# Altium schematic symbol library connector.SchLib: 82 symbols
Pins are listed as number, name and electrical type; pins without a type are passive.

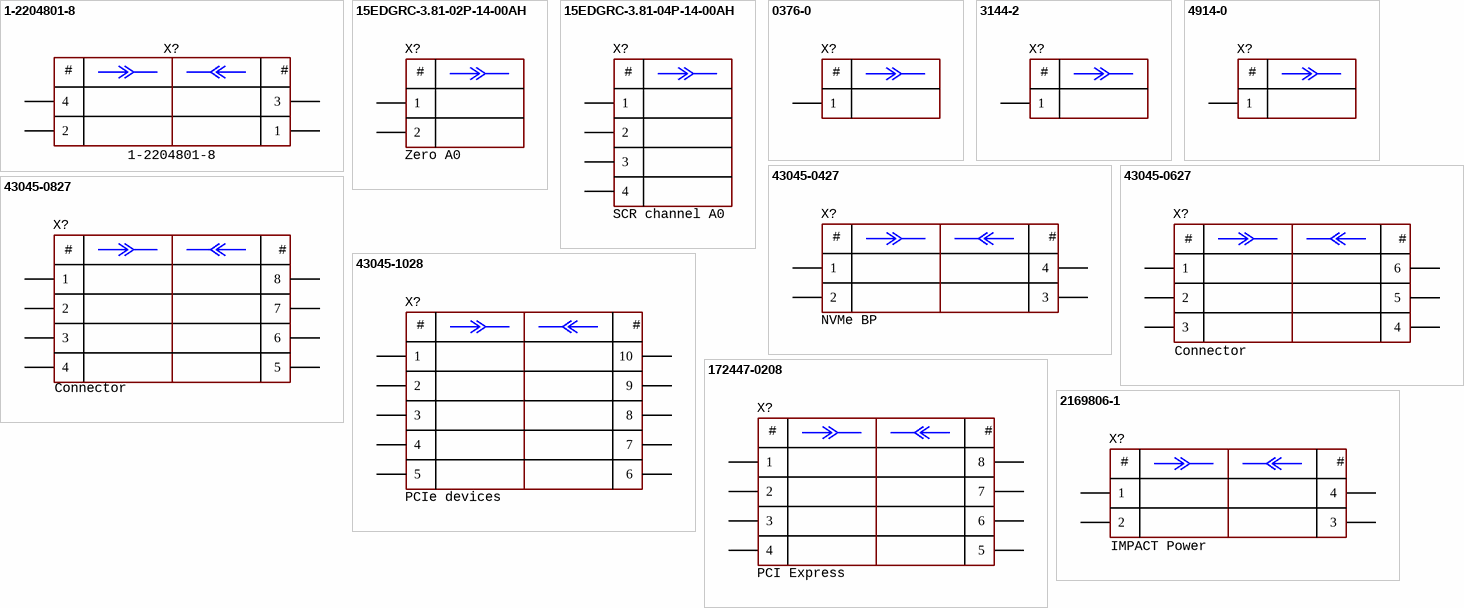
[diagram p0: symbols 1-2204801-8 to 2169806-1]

## 1-2204801-8
designator X?
MicroFit, 4 pins, pitch 3.0 mm, 600V, 12.5A/pin, -40...+105°C; Manufacturer: TE Connectivity
footprint CON: 1-2204801-8 (MicroFit)
pins: 1, 2, 3, 4

## 15EDGRC-3.81-02P-14-00AH
designator X?, comment Zero A0
Terminal, 2 pins, pitch 3.81 mm, 8A/pin, 500VAC; PartNumber: 15EDGRC-3.81-02P-14-00AH; Manufacturer: Degson; Pitch: 3.81 mm
footprint CON: 15EDGRC-3.81-02P-14-00AH (Degson) (PLS-4 pin header)
pins: 1, 2

## 15EDGRC-3.81-04P-14-00AH
designator X?, comment SCR channel A0
Terminal, 4 pins, pitch 3.81 mm, 8A/pin, 500VAC; Manufacturer: Degson; PartNumber: 15EDGRC-3.81-04P-14-00AH; Pitch: 3.81 mm
footprint CON: 15EDGRC-3.81-04P-14-00AH (Degson) (PLS-4 pin header)
pins: 1, 2, 3 (power), 4 (power)

## 0376-0
designator X?
Power Pin, SMT, -55...+150°C; PartNumber: 0376-0-43-80-07-27-10-0; Manufacturer: Mill-Max
footprint CON: 0376-0 (Mill-Max)
pins: 1

## 3144-2
designator X?
Power Pin, SMT, -55...+150°C; PartNumber: 3144-2-00-15-00-00-08-0; Manufacturer: Mill-Max
footprint CON: 3144-2 (Mill-Max)
pins: 1

## 4914-0
designator X?
Power Pin, SMT, -55...+150°C; PartNumber: 4914-0-00-15-00-00-03-0; Manufacturer: Mill-Max
footprint CON: 4914-0 (Mill-Max)
pins: 1

## 43045-0427
designator X?, comment NVMe BP
MicroFit, 4 pins, pitch 3.0 mm, 600V, 8.5A/pin, -40...+105°C; PartNumber: 43045-0427; Manufacturer: Molex
footprint CON: 43045-0427 (MicroFit)
pins: 1, 2, 3, 4

## 43045-0627
designator X?, comment Connector
MicroFit, 6 pins, pitch 3.0 mm, 600V, 8.5A/pin, -40...+105°C; PartNumber: 43045-0627; Manufacturer: Molex
footprint CON: 43045-0628 (MicroFit)
pins: 1, 2, 3, 4, 5, 6

## 43045-0827
designator X?, comment Connector
MicroFit, 8 pins, pitch 3.0 mm, 600V, 8.5A/pin, -40...+105°C; PartNumber: 43045-0827; Manufacturer: Molex
footprint CON: 43045-0828 (MicroFit)
pins: 1, 2, 3, 4, 5, 6, 7, 8

## 43045-1028
designator X?, comment PCIe devices
MicroFit, 10 pins, pitch 3.0 mm, 600V, 8.5A/pin, -40...+105°C; PartNumber: 43045-1028; Manufacturer: Molex
footprint CON: 43045-1028 (MicroFit)
pins: 1, 2, 3, 4, 5, 6, 7, 8, 9, 10

## 172447-0208
designator X?, comment PCI Express
MiniFit, 8 pins, pitch 4.2 mm, 600V, 9A/pin, -40...+105°C; Manufacturer: Molex; PartNumber: 172447-0208; Manufacturer: Molex Waldom
footprint CON: 172447-0208
pins: 1, 2, 3, 4, 5, 6, 7, 8

## 2169806-1
designator X?  Package: IMPACT Power  (hidden comment: 2169806-1)
IMPACT, 4 pins, pitch 5.2 mm, 48V, 15A/pin, -55...+85°C; Manufacturer: TE Connectivity
footprint CON: 2169806-1
pins: 1, 2, 3, 4

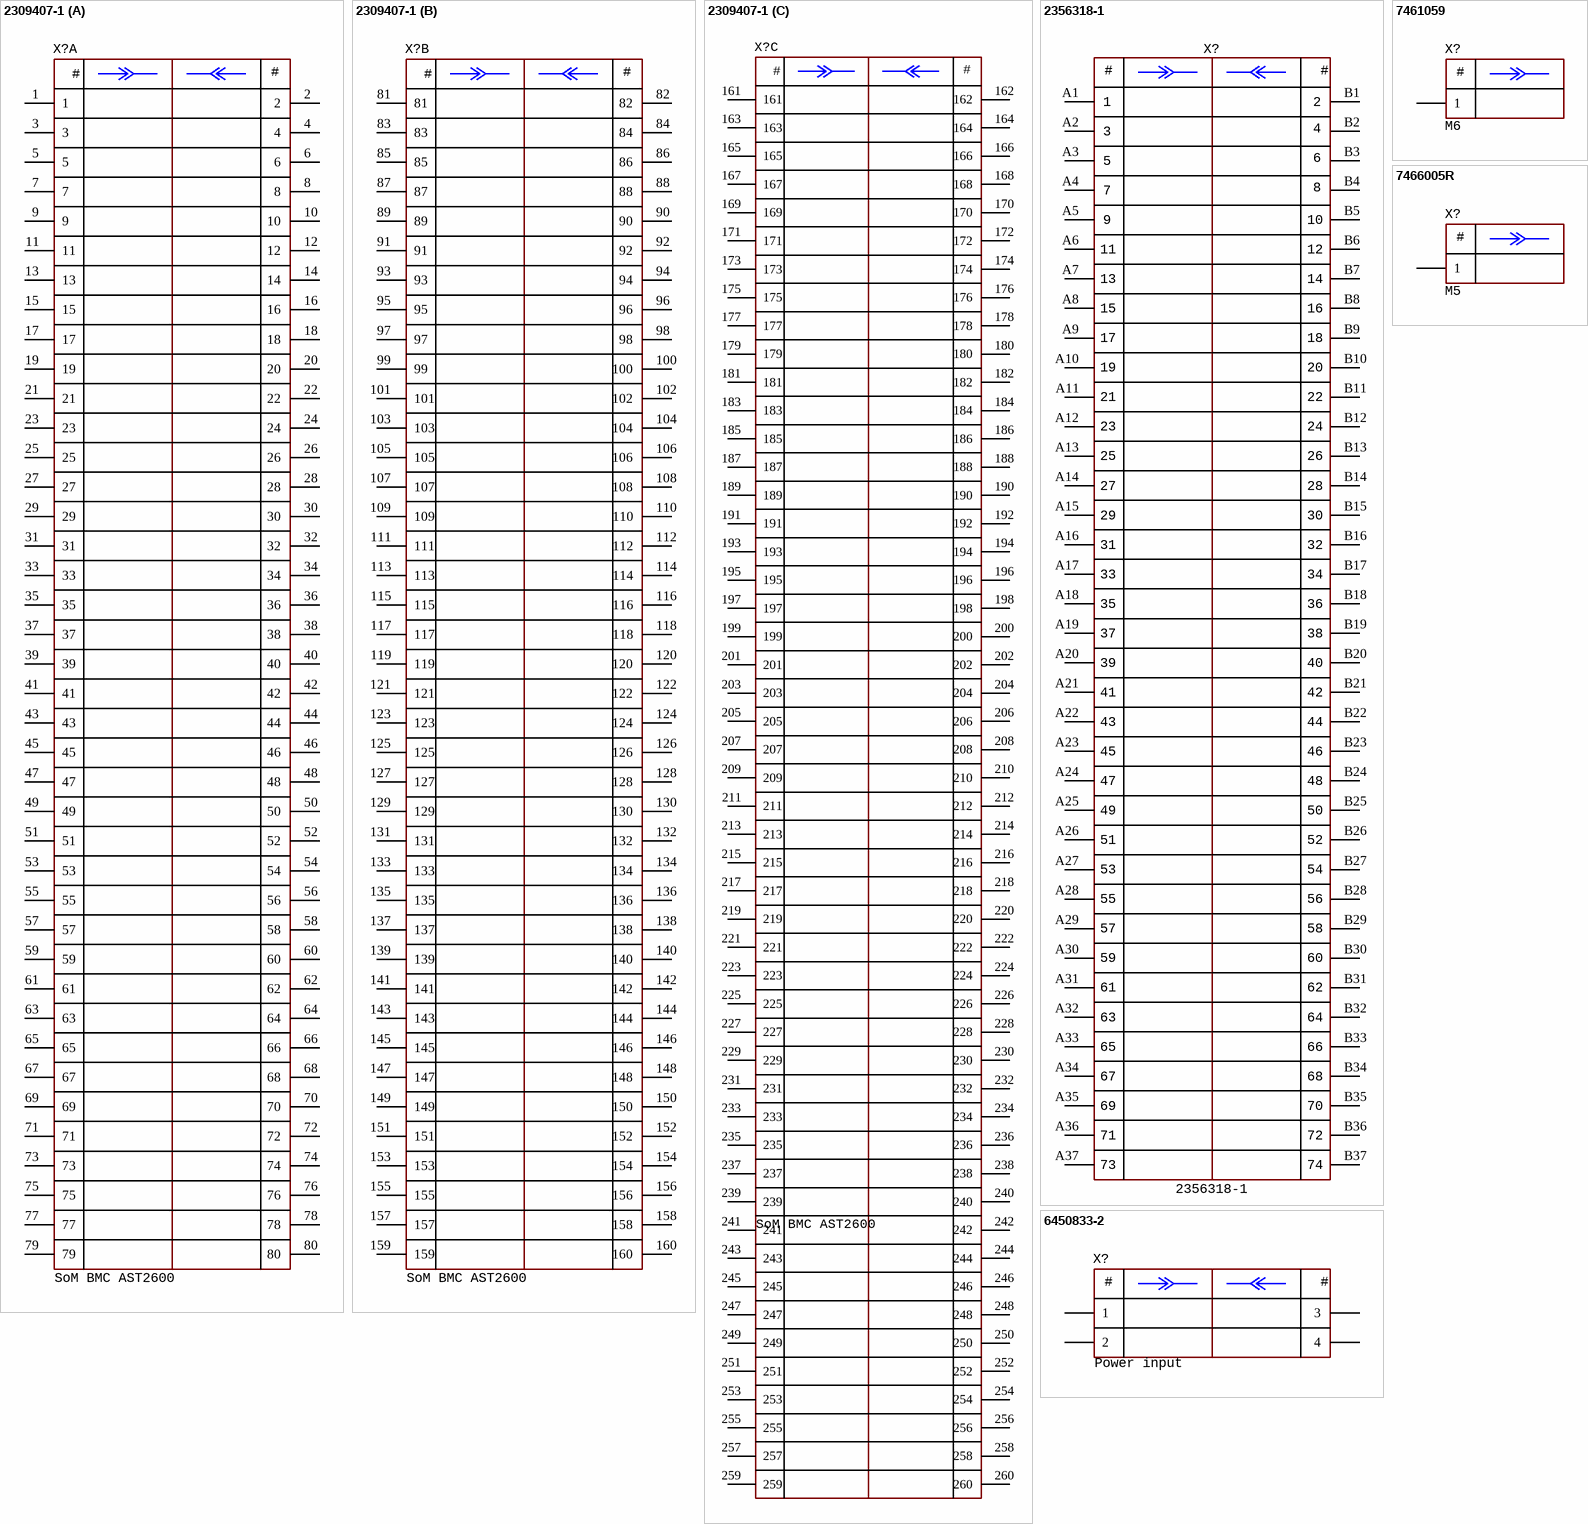
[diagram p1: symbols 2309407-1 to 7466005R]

## 2309407-1
designator X?, comment SoM BMC AST2600
SODIMM DDR4, 260 pins, pitch 0.5 mm, 0.5A/pin, Right Angle, -55...+85C; Manufacturer: TE connectivity; PartNumber: 2309407-1; Pitch: 0.5mm
footprint CON: 2309407-1 (TE, SODIMM DDR4)
part A pins: 1, 2, 3, 4, 5, 6, 7, 8, 9, 10, 11, 12, 13, 14, 15, 16, 17, 18, 19, 20, 21, 22, 23, 24, 25, 26, 27, 28, 29, 30, 31, 32, 33, 34, 35, 36, 37, 38, 39, 40, 41, 42, 43, 44, 45, 46, 47, 48, 49, 50, 51, 52, 53, 54, 55, 56, 57, 58, 59, 60, 61, 62, 63, 64, 65, 66, 67, 68, 69, 70, 71, 72, 73, 74, 75, 76, 77, 78, 79, 80
part B pins: 81, 82, 83, 84, 85, 86, 87, 88, 89, 90, 91, 92, 93, 94, 95, 96, 97, 98, 99, 100, 101, 102, 103, 104, 105, 106, 107, 108, 109, 110, 111, 112, 113, 114, 115, 116, 117, 118, 119, 120, 121, 122, 123, 124, 125, 126, 127, 128, 129, 130, 131, 132, 133, 134, 135, 136, 137, 138, 139, 140, 141, 142, 143, 144, 145, 146, 147, 148, 149, 150, 151, 152, 153, 154, 155, 156, 157, 158, 159, 160
part C pins: 161, 162, 163, 164, 165, 166, 167, 168, 169, 170, 171, 172, 173, 174, 175, 176, 177, 178, 179, 180, 181, 182, 183, 184, 185, 186, 187, 188, 189, 190, 191, 192, 193, 194, 195, 196, 197, 198, 199, 200, 201, 202, 203, 204, 205, 206, 207, 208, 209, 210, 211, 212, 213, 214, 215, 216, 217, 218, 219, 220, 221, 222, 223, 224, 225, 226, 227, 228, 229, 230, 231, 232, 233, 234, 235, 236, 237, 238, 239, 240, 241, 242, 243, 244, 245, 246, 247, 248, 249, 250, 251, 252, 253, 254, 255, 256, 257, 258, 259, 260

## 2356318-1
designator X?
SlimSAS, x8 line, 74 pins, 0.5A/pin, SFF-8654, vertical, -55...+85°C; Manufacturer: TE connectivity; Manufacturer: TE Connectivity AMP; Multichannel: 74pin
footprint CON: 2356318-1 (SlimSAS)
pins: A1, A2, A3, A4, A5, A6, A7, A8, A9, A10, A11, A12, A13, A14, A15, A16, A17, A18, A19, A20, A21, A22, A23, A24, A25, A26, A27, A28, A29, A30, A31, A32, A33, A34, A35, A36, A37, B1, B2, B3, B4, B5, B6, B7, B8, B9, B10, B11, B12, B13, B14, B15, B16, B17, B18, B19, B20, B21, B22, B23, B24, B25, B26, B27, B28, B29, B30, B31, B32, B33, B34, B35, B36, B37

## 6450833-2
designator X?, comment Power input
Power, 4 pins, pitch 6.35 mm, 200V, 50A/pin, -40...+125°C; PartNumber: 6450833-2; Manufacturer: TE connectivity
footprint CON: 6450833-2
pins: 1, 2, 3, 4

## 7461059
designator X?, comment M6
Power, 240A, screw M6, SMT, -55...+150°C; Manufacturer: Wurth; PartNumber: 7461059; Manufacturer: Wurth Electronics; Manufacturer Part Number: 746105-9
footprint CON: 7461059 (Wurth, connector)
pins: 1

## 7466005R
designator X?, comment M5
Power, 70A, screw M5, SMT, -55...+150°C; PartNumber: 7466005R; Manufacturer: Wurth; Manufacturer: Wurth Electronics
footprint CON: 7466005R (Wurth, connector)
pins: 1

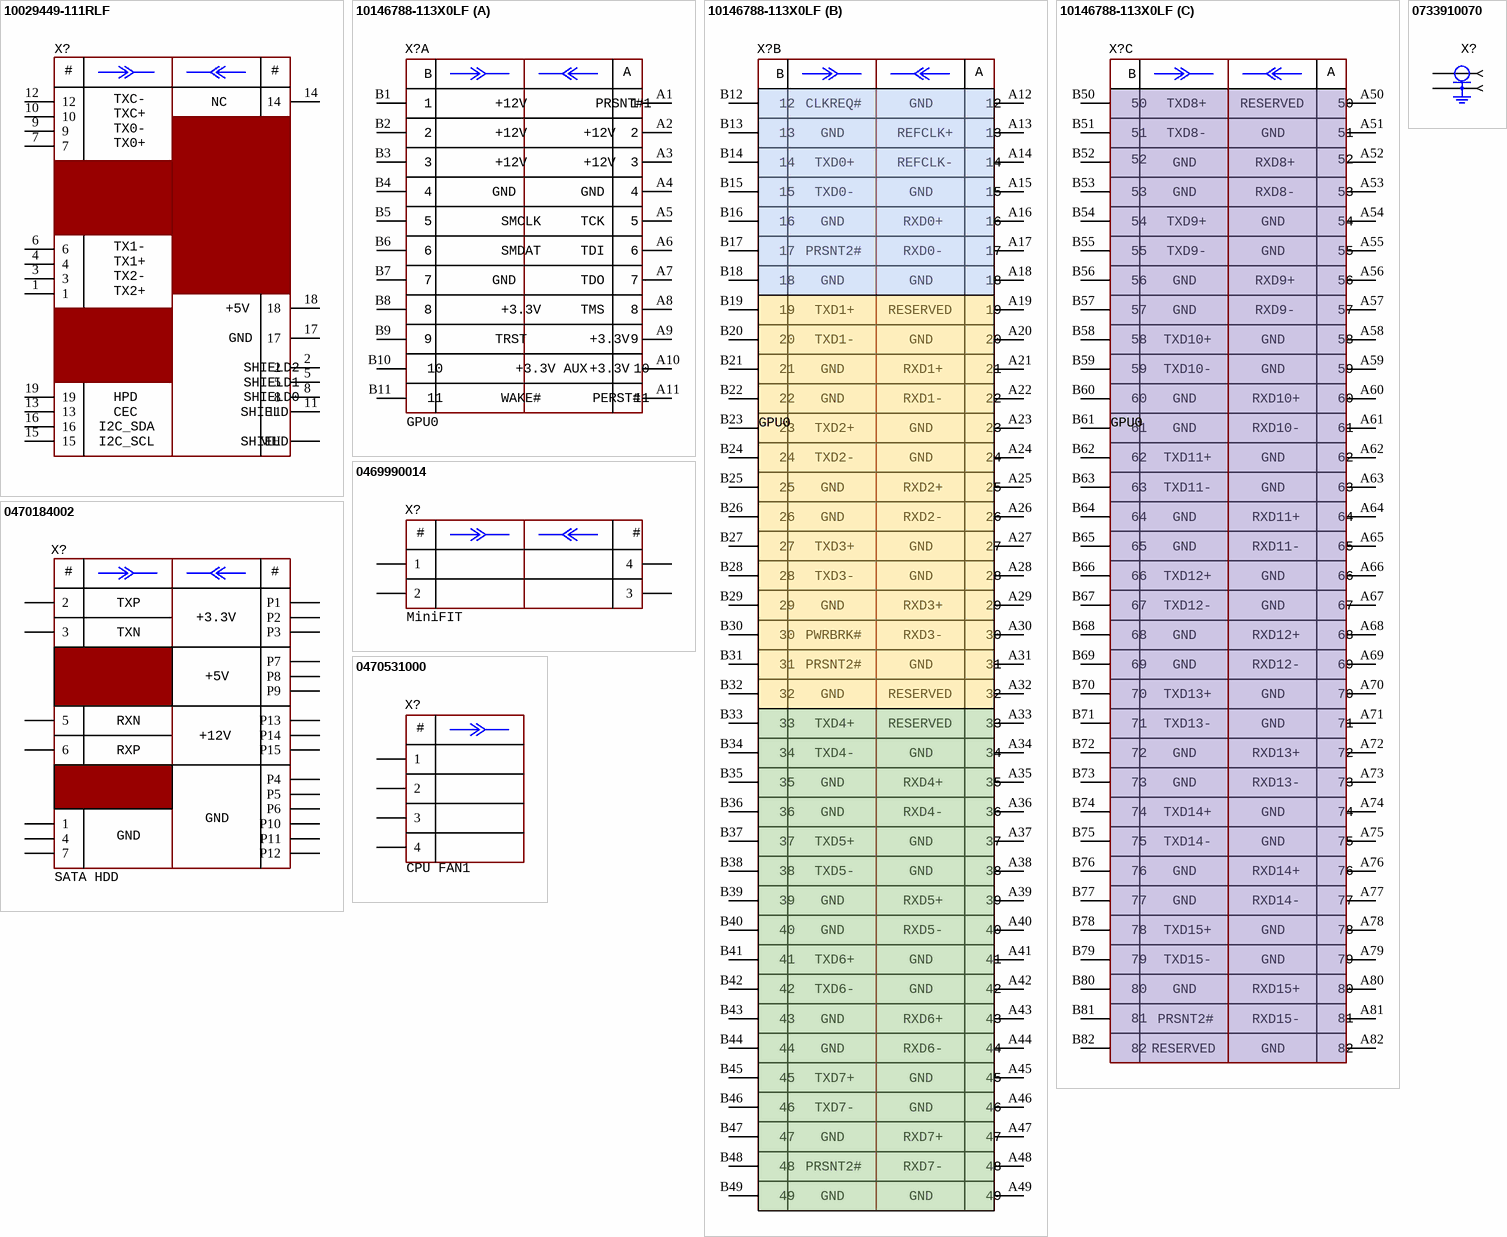
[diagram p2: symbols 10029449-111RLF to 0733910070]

## 10029449-111RLF
designator X?  (value not drawn)
HDMI 1.4, 0.5A/pin, 19 pins, -20...+85°C
footprint CON: HDMI_10029449-111RLF (HDMI 1.4, Amphenol)
pins: 1, 2, 3, 4, 5, 6, 7, 8, 9, 10, 11, 12, 13, 14, 15, 16, 17, 18, 19, MH (power)

## 10146788-113X0LF
designator X?, comment GPU0
PCI Express, Gen 4.0, x16 lines, 16 GT/s, 164 pins, pitch 1.0 mm, -40...+85°C; Manufacturer: Amphenol; PartNumber: 10146788-113X0LF
footprint CON: 10146788-113X0LF (PCIe gen 4, Amphenol)
part A pins: A1, A2, A3, A4, A5, A6, A7, A8, A9, A10, A11, B1, B2, B3, B4, B5, B6, B7, B8, B9, B10, B11
part B pins: A12, A13, A14, A15, A16, A17, A18, A19, A20, A21, A22, A23, A24, A25, A26, A27, A28, A29, A30, A31, A32, A33, A34, A35, A36, A37, A38, A39, A40, A41, A42, A43, A44, A45, A46, A47, A48, A49, B12, B13, B14, B15, B16, B17, B18, B19, B20, B21, B22, B23, B24, B25, B26, B27, B28, B29, B30, B31, B32, B33, B34, B35, B36, B37, B38, B39, B40, B41, B42, B43, B44, B45, B46, B47, B48, B49
part C pins: A50, A51, A52, A53, A54, A55, A56, A57, A58, A59, A60, A61, A62, A63, A64, A65, A66, A67, A68, A69, A70, A71, A72, A73, A74, A75, A76, A77, A78, A79, A80, A81, A82, B50, B51, B52, B53, B54, B55, B56, B57, B58, B59, B60, B61, B62, B63, B64, B65, B66, B67, B68, B69, B70, B71, B72, B73, B74, B75, B76, B77, B78, B79, B80, B81, B82

## 0469990014
designator X?, comment MiniFIT
MiniFit, 4 pins, pitch 4.2 mm, 600V, 20A/pin, -40...+105°C; PartNumber: 0469990014; Manufacturer: Molex; Manufacturer Part Number: 172447-0206
footprint CON: 0469990014 (MiniFitm 4 pins, 90)
pins: 1, 2, 3, 4

## 0470184002
designator X?, comment SATA HDD
SATA HDD, 7+15 pins, 24 GT/s, Right angle, -55...+85°C; Manufacturer: Molex; PartNumber: 0470184002; Multichannel: 74pin
footprint CON: 0470184002 (Molex, SATA HDD)
pins: 1, 2, 3, 4, 5, 6, 7, P1, P2, P3, P4, P5, P6, P7, P8, P9, P10, P11, P12, P13, P14, P15

## 0470531000
designator X?, comment CPU FAN1
Fan, 4 pins, pitch 2.54 mm, 3A/pins, 600V, -40...+125°C; PartNumber: 0470531000; Manufacturer: Molex; Pitch: 2.54mm
footprint CON: 0470531000 (Molex, CPU fan)
pins: 1, 2, 3, 4 (power)

## 0733910070
designator X?, comment SMA  (value not drawn)
SMA, RF type, 50 Ohms, 18GHz, -40...+125°C; PartNumber: 0733910070; Manufacturer: Molex
footprint CON: SMA
pins: 1, 2

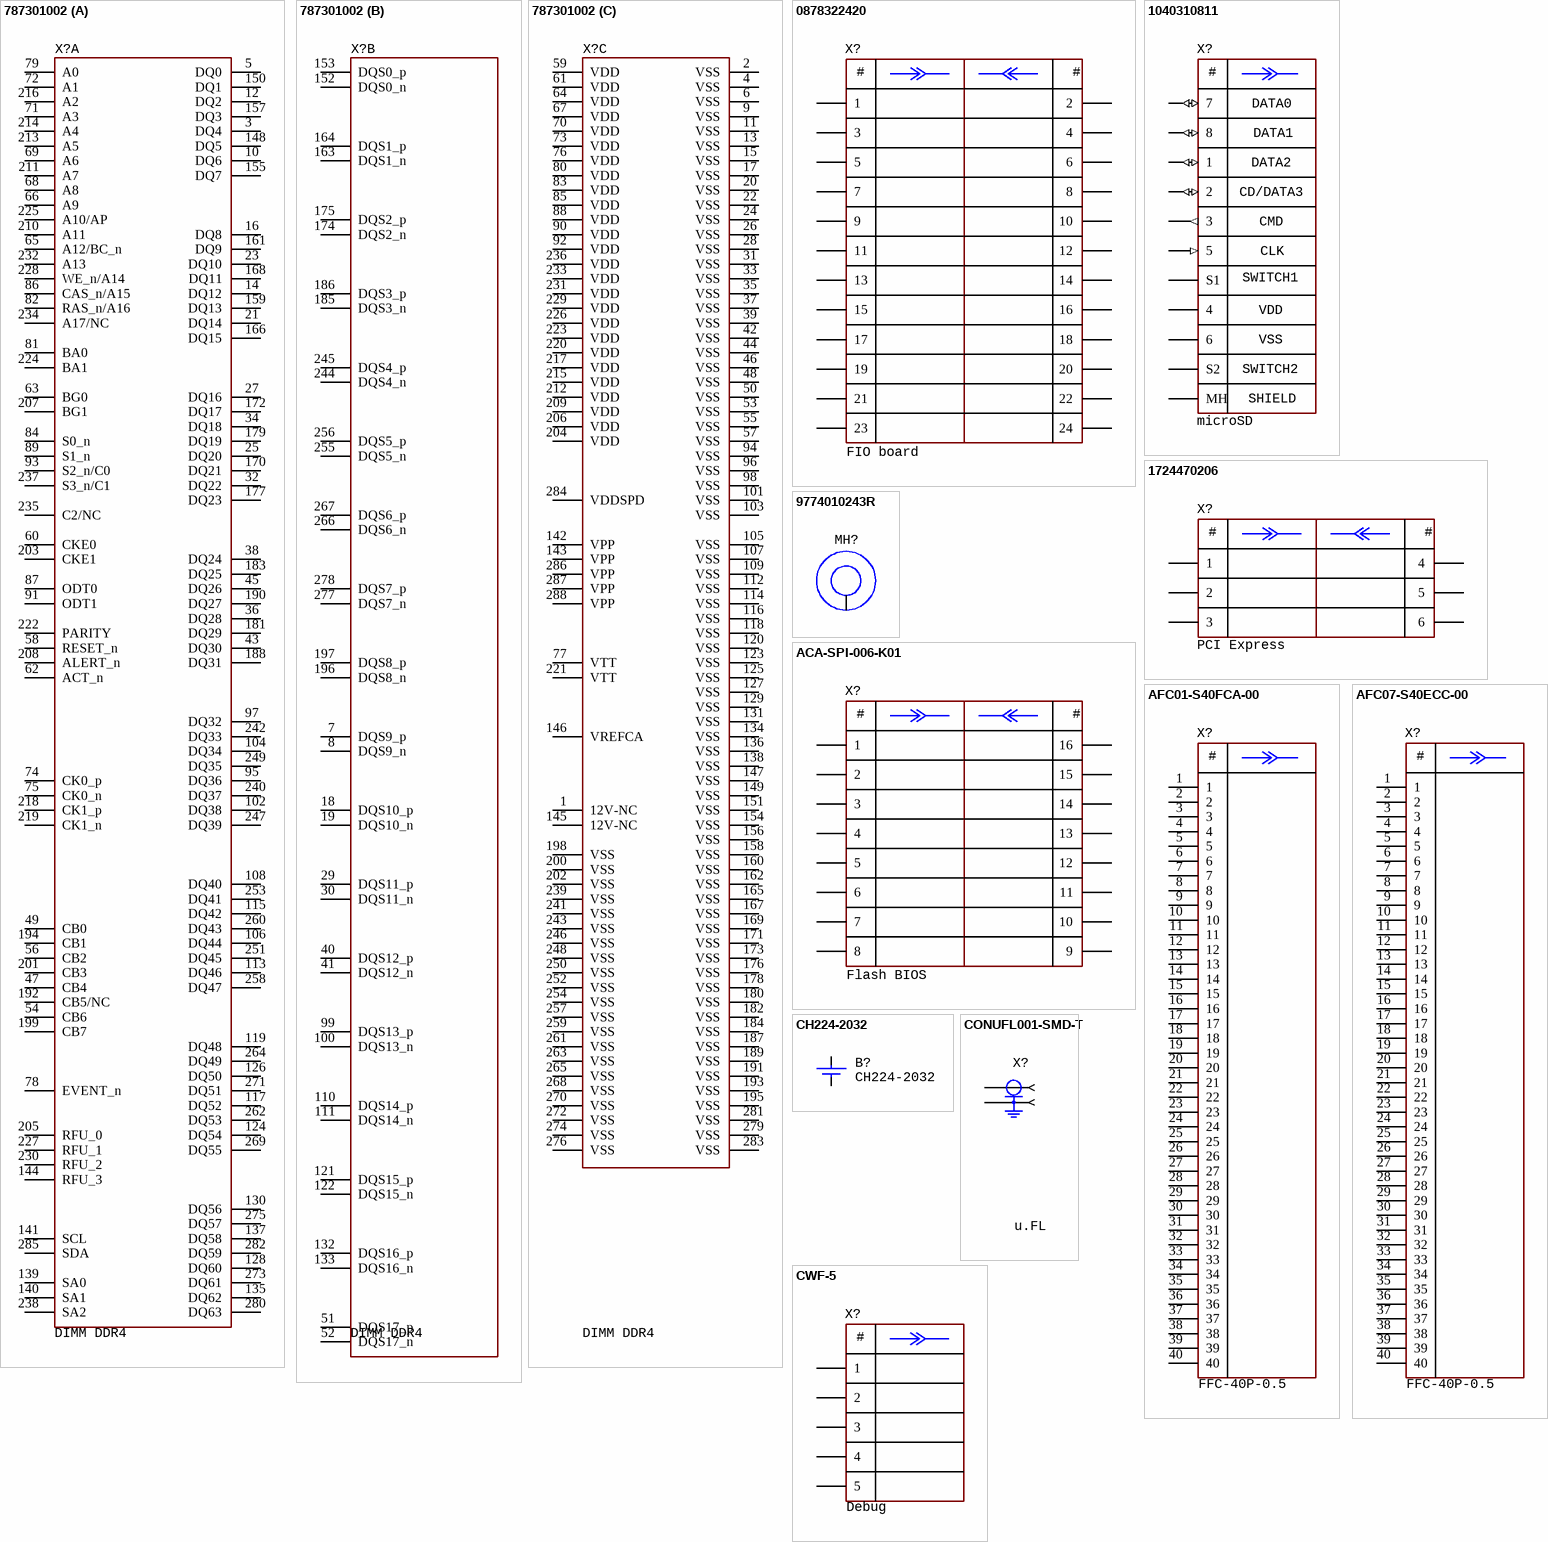
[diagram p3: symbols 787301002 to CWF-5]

## 787301002
designator X?, comment DIMM DDR4
DIMM DDR4, 288 pins, pitch 0.85 mm, 0.75A/pitch, -55...+85°C; Manufacturer: Molex; PartNumber: 787301002; Manufacturer: Molex Waldom; Manufacturer Part Number: 78730-1002
footprint CON: 787301002 (Molex, DIMM DDR4) (DIMM DDR4 288 pins)
part A pins: 3 DQ4, 5 DQ0, 10 DQ6, 12 DQ2, 14 DQ12, 16 DQ8, 21 DQ14, 23 DQ10, 25 DQ20, 27 DQ16, 32 DQ22, 34 DQ18, 36 DQ28, 38 DQ24, 43 DQ30, 45 DQ26, 47 CB4, 49 CB0, 54 CB6, 56 CB2, 58 RESET_n, 60 CKE0, 62 ACT_n, 63 BG0, 65 A12/BC_n, 66 A9, 68 A8, 69 A6, 71 A3, 72 A1, 74 CK0_p, 75 CK0_n, 78 EVENT_n, 79 A0, 81 BA0, 82 RAS_n/A16, 84 S0_n, 86 CAS_n/A15, 87 ODT0, 89 S1_n, 91 ODT1, 93 S2_n/C0, 95 DQ36, 97 DQ32, 102 DQ38, 104 DQ34, 106 DQ44, 108 DQ40, 113 DQ46, 115 DQ42, 117 DQ52, 119 DQ48, 124 DQ54, 126 DQ50, 128 DQ60, 130 DQ56, 135 DQ62, 137 DQ58, 139 SA0, 140 SA1, 141 SCL, 144 RFU_3, 148 DQ5, 150 DQ1, 155 DQ7, 157 DQ3, 159 DQ13, 161 DQ9, 166 DQ15, 168 DQ11, 170 DQ21, 172 DQ17, 177 DQ23, 179 DQ19, 181 DQ29, 183 DQ25, 188 DQ31, 190 DQ27, 192 CB5/NC, 194 CB1, 199 CB7, 201 CB3, 203 CKE1, 205 RFU_0, 207 BG1, 208 ALERT_n, 210 A11, 211 A7, 213 A5, 214 A4, 216 A2, 218 CK1_p, 219 CK1_n, 222 PARITY, 224 BA1, 225 A10/AP, 227 RFU_1, 228 WE_n/A14, 230 RFU_2, 232 A13, 234 A17/NC, 235 C2/NC, 237 S3_n/C1, 238 SA2, 240 DQ37, 242 DQ33, 247 DQ39, 249 DQ35, 251 DQ45, 253 DQ41, 258 DQ47, 260 DQ43, 262 DQ53, 264 DQ49, 269 DQ55, 271 DQ51, 273 DQ61, 275 DQ57, 280 DQ63, 282 DQ59, 285 SDA
part B pins: 7 DQS9_p, 8 DQS9_n, 18 DQS10_p, 19 DQS10_n, 29 DQS11_p, 30 DQS11_n, 40 DQS12_p, 41 DQS12_n, 51 DQS17_p, 52 DQS17_n, 99 DQS13_p, 100 DQS13_n, 110 DQS14_p, 111 DQS14_n, 121 DQS15_p, 122 DQS15_n, 132 DQS16_p, 133 DQS16_n, 152 DQS0_n, 153 DQS0_p, 163 DQS1_n, 164 DQS1_p, 174 DQS2_n, 175 DQS2_p, 185 DQS3_n, 186 DQS3_p, 196 DQS8_n, 197 DQS8_p, 244 DQS4_n, 245 DQS4_p, 255 DQS5_n, 256 DQS5_p, 266 DQS6_n, 267 DQS6_p, 277 DQS7_n, 278 DQS7_p
part C pins: 1 12V-NC, 2 VSS, 4 VSS, 6 VSS, 9 VSS, 11 VSS, 13 VSS, 15 VSS, 17 VSS, 20 VSS, 22 VSS, 24 VSS, 26 VSS, 28 VSS, 31 VSS, 33 VSS, 35 VSS, 37 VSS, 39 VSS, 42 VSS, 44 VSS, 46 VSS, 48 VSS, 50 VSS, 53 VSS, 55 VSS, 57 VSS, 59 VDD, 61 VDD, 64 VDD, 67 VDD, 70 VDD, 73 VDD, 76 VDD, 77 VTT, 80 VDD, 83 VDD, 85 VDD, 88 VDD, 90 VDD, 92 VDD, 94 VSS, 96 VSS, 98 VSS, 101 VSS, 103 VSS, 105 VSS, 107 VSS, 109 VSS, 112 VSS, 114 VSS, 116 VSS, 118 VSS, 120 VSS, 123 VSS, 125 VSS, 127 VSS, 129 VSS, 131 VSS, 134 VSS, 136 VSS, 138 VSS, 142 VPP, 143 VPP, 145 12V-NC, 146 VREFCA, 147 VSS, 149 VSS, 151 VSS, 154 VSS, 156 VSS, 158 VSS, 160 VSS, 162 VSS, 165 VSS, 167 VSS, 169 VSS, 171 VSS, 173 VSS, 176 VSS, 178 VSS, 180 VSS, 182 VSS, 184 VSS, 187 VSS, 189 VSS, 191 VSS, 193 VSS, 195 VSS, 198 VSS, 200 VSS, 202 VSS, 204 VDD, 206 VDD, 209 VDD, 212 VDD, 215 VDD, 217 VDD, 220 VDD, 221 VTT, 223 VDD, 226 VDD, 229 VDD, 231 VDD, 233 VDD, 236 VDD, 239 VSS, 241 VSS, 243 VSS, 246 VSS, 248 VSS, 250 VSS, 252 VSS, 254 VSS, 257 VSS, 259 VSS, 261 VSS, 263 VSS, 265 VSS, 268 VSS, 270 VSS, 272 VSS, 274 VSS, 276 VSS, 279 VSS, 281 VSS, 283 VSS, 284 VDDSPD, 286 VPP, 287 VPP, 288 VPP

## 0878322420
designator X?, comment FIO board
24 pins, 2 rows, vertical, pitch 2.0mm, 800VAC, 1A, -55...+105°C; PartNumber: 0878322420; Manufacturer: Molex
footprint CON: 0878322420 (Molex)
pins: 1, 2, 3, 4, 5, 6, 7, 8, 9, 10, 11, 12, 13, 14, 15, 16, 17, 18, 19, 20, 21, 22, 23, 24

## 1040310811
designator X?  CommentText: microSD
Micro SD card; Manufacturer: Molex; PartNumber: 1040310811
footprint CON: 1040310811 (Molex, SD card)
pins: 1 (io), 2 (io), 3 (out), 4 (power), 5 (in), 6 (power), 7 (io), 8 (io), MH (power), S1 (power), S2 (power)

## 1724470206
designator X?, comment PCI Express
MiniFit, 6 pins, pitch 4.2 mm, 600V, 20A/pin, -40...+105°C; PartNumber: 1724470206; Manufacturer: Molex; Manufacturer Part Number: 172447-0206
footprint CON: 1724470206 (MiniFit)
pins: 1, 2, 3, 4, 5, 6

## 9774010243R
designator MH?
Heatsink, screw M2, SMT, -55...+150°C; PartNumber: 9774010243R; Manufacturer: Wurth
footprint CON: 9774010243R (M2 screw)
pins: 1

## ACA-SPI-006-K01
designator X?, comment Flash BIOS
SOIC-16 panel, pitch 1.27; PartNumber: ACA-SPI-006-K01; Manufacturer: LOTES
footprint CON: ACA-SPI-006-K01 (FLASH) (SOIC-16 panel, pitch 1.27 mm)
pins: 1, 2, 3, 4, 5, 6, 7, 8, 9, 10, 11, 12, 13, 14, 15, 16

## AFC01-S40FCA-00
designator X?, comment FFC-40P-0.5
FFC, 40 pins, pitch 0.5 mm, bottom, -40...+85C; Manufacturer: JUSHUO; PartNumber: AFC01-S40FCA-00; TypeConnector: FFC/FPC
footprint CON: FFC/FPC-40-0.5
pins: 1, 2, 3, 4, 5, 6, 7, 8, 9, 10, 11, 12, 13, 14, 15, 16, 17, 18, 19, 20, 21, 22, 23, 24, 25, 26, 27, 28, 29, 30, 31, 32, 33, 34, 35, 36, 37, 38, 39, 40

## AFC07-S40ECC-00
designator X?, comment FFC-40P-0.5
FFC, 40 pins, pitch 0.5 mm, top, -40...+85C; Manufacturer: JUSHUO; PartNumber: AFC07-S40ECC-00; TypeConnector: FFC/FPC
footprint CON: FFC/FPC-40-0.5
pins: 1, 2, 3, 4, 5, 6, 7, 8, 9, 10, 11, 12, 13, 14, 15, 16, 17, 18, 19, 20, 21, 22, 23, 24, 25, 26, 27, 28, 29, 30, 31, 32, 33, 34, 35, 36, 37, 38, 39, 40

## CH224-2032
designator B?
Battery, type CR2032, -40...+105°C; Manufacturer: KLS; Manufacturer: NEXcell; TypeConnector: Single battery CR2032
footprint CON: CH224-2032 (Holder CR2032)
pins: 1 + (power), 2 - (power)

## CONUFL001-SMD-T
designator X?, comment u.FL
u.FL, 2 pins, RF type, 50 Ohms, 6GHz, -40...+125°C; PartNumber: CONUFL001-SMD-T; Manufacturer: Linx
footprint CON: u.Fl
pins: 1, 2

## CWF-5
designator X?, comment Debug
CWF series, 5 pins, pitch 2.5 mm, 3A/pin, -40...+125°C; Manufacturer: KLS; PartNumber: CWF-5; Pitch: 2.5 mm
footprint CON: CWF-5
pins: 1, 2, 3 (power), 4 (power), 5 (power)

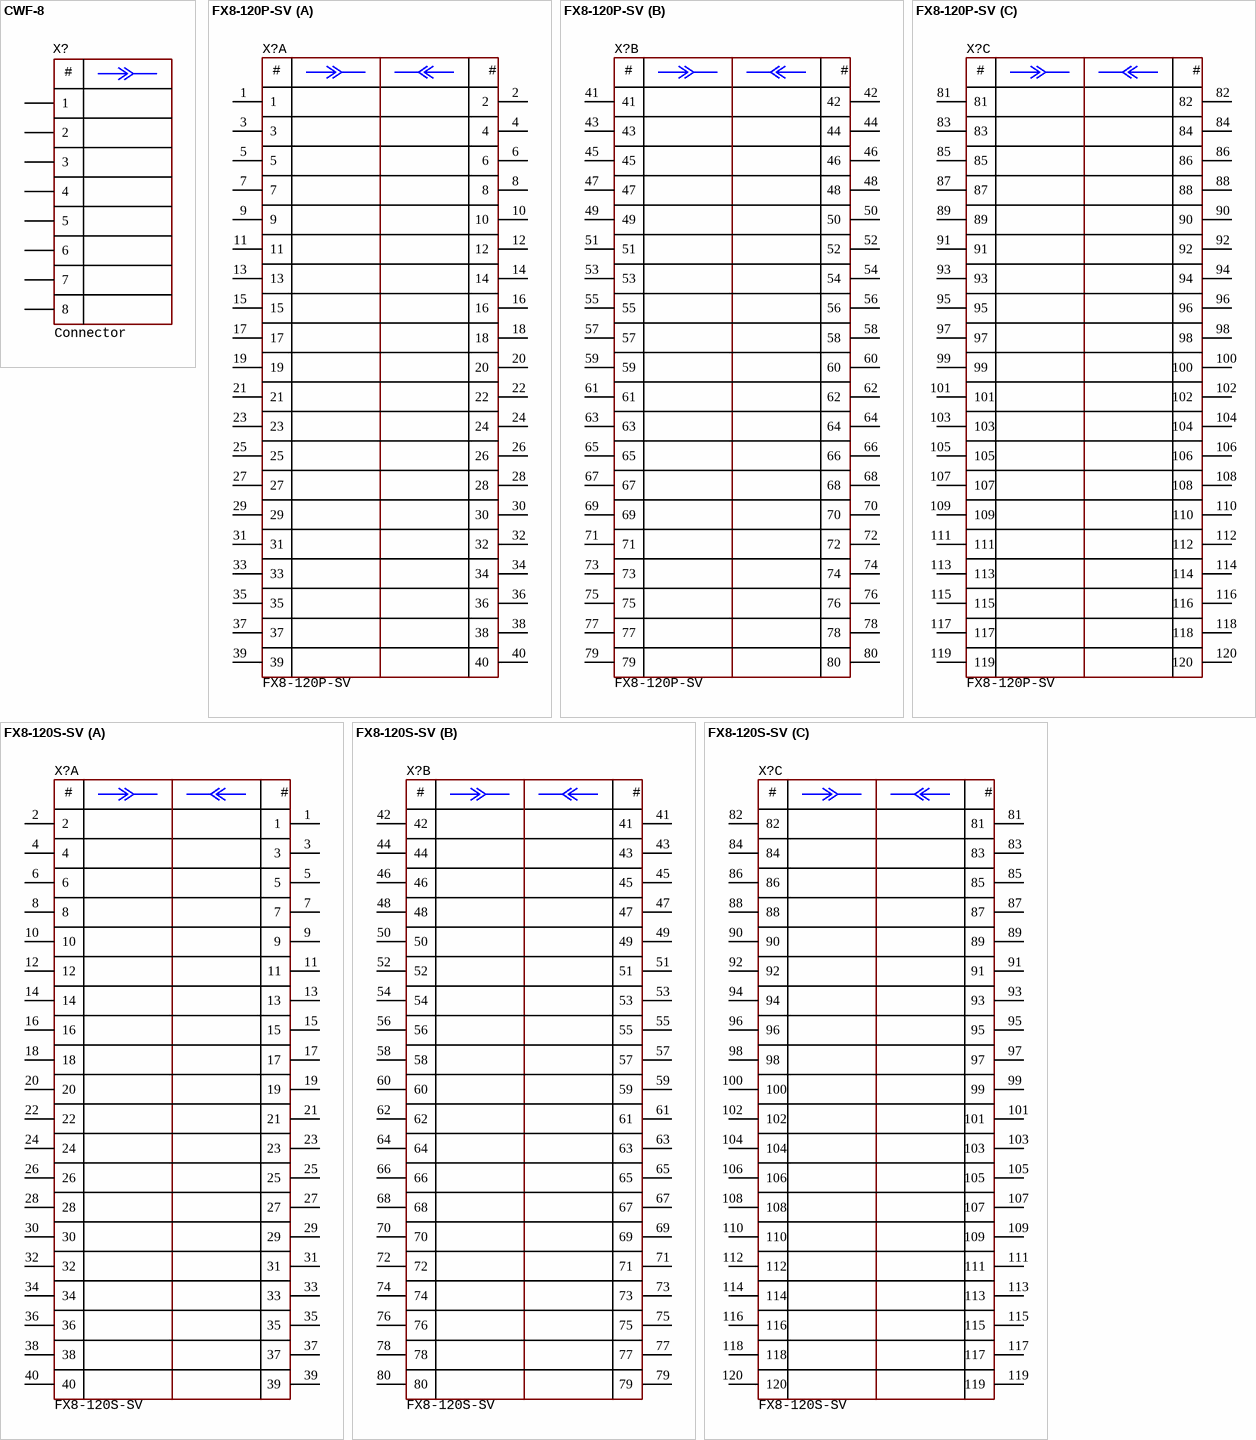
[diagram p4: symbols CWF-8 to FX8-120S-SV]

## CWF-8
designator X?, comment Connector
8 pins, pitch 2.54 mm, 500VAC, 3A/pin, -40...+85°C; Manufacturer: Connfly; PartNumber: CWF-8; Pitch: 2.54mm
footprint CON: CWF-8
pins: 1, 2, 3 (power), 4 (power), 5 (power), 6 (power), 7 (power), 8 (power)

## FX8-120P-SV
designator X?
High speed IO, 120 pins, pitch 0.6 mm, h=3 mm, -55...+85°C; Manufacturer: Hirose; Pitch: 0.6 mm
footprint CON: FX8-120P-SV
part A pins: 1, 2, 3, 4, 5, 6, 7, 8, 9, 10, 11, 12, 13, 14, 15, 16, 17, 18, 19, 20, 21, 22, 23, 24, 25, 26, 27, 28, 29, 30, 31, 32, 33, 34, 35, 36, 37, 38, 39, 40
part B pins: 41, 42, 43, 44, 45, 46, 47, 48, 49, 50, 51, 52, 53, 54, 55, 56, 57, 58, 59, 60, 61, 62, 63, 64, 65, 66, 67, 68, 69, 70, 71, 72, 73, 74, 75, 76, 77, 78, 79, 80
part C pins: 81, 82, 83, 84, 85, 86, 87, 88, 89, 90, 91, 92, 93, 94, 95, 96, 97, 98, 99, 100, 101, 102, 103, 104, 105, 106, 107, 108, 109, 110, 111, 112, 113, 114, 115, 116, 117, 118, 119, 120

## FX8-120S-SV
designator X?
High speed IO, 120 pins, pitch 0.6 mm, h=3 mm, -55...+85°C; Manufacturer: Hirose; Pitch: 0.6 mm
footprint CON: FX8-120S-SV
part A pins: 1, 2, 3, 4, 5, 6, 7, 8, 9, 10, 11, 12, 13, 14, 15, 16, 17, 18, 19, 20, 21, 22, 23, 24, 25, 26, 27, 28, 29, 30, 31, 32, 33, 34, 35, 36, 37, 38, 39, 40
part B pins: 41, 42, 43, 44, 45, 46, 47, 48, 49, 50, 51, 52, 53, 54, 55, 56, 57, 58, 59, 60, 61, 62, 63, 64, 65, 66, 67, 68, 69, 70, 71, 72, 73, 74, 75, 76, 77, 78, 79, 80
part C pins: 81, 82, 83, 84, 85, 86, 87, 88, 89, 90, 91, 92, 93, 94, 95, 96, 97, 98, 99, 100, 101, 102, 103, 104, 105, 106, 107, 108, 109, 110, 111, 112, 113, 114, 115, 116, 117, 118, 119, 120

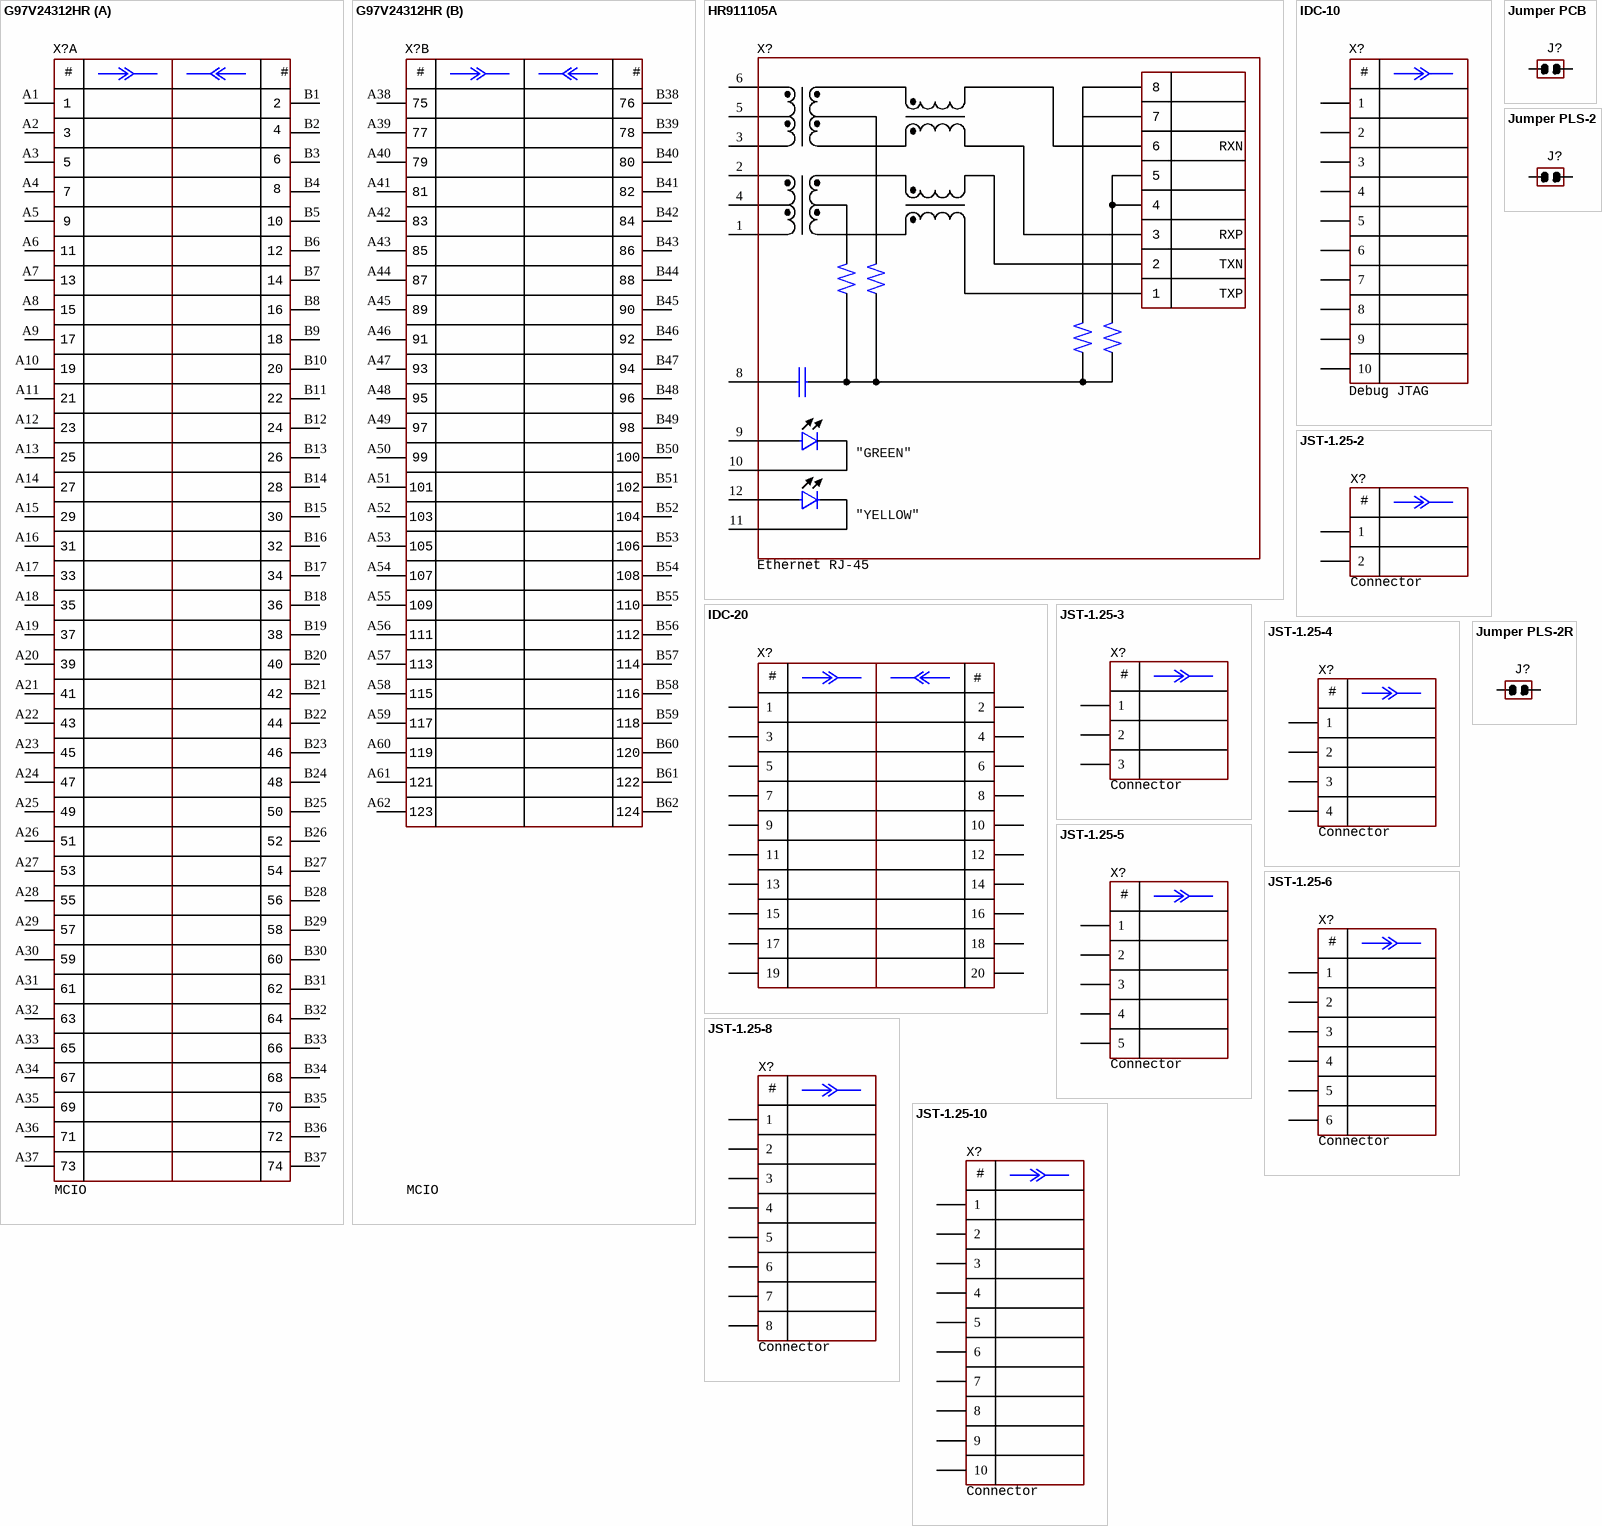
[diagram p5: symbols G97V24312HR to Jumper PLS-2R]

## G97V24312HR
designator X?, comment MCIO
MCIO, 124 pins, 56Gb/s, 85 Omhs, vertical, -55...+85°C; Manufacturer: Amphenol; PartNumber: G97V24312HR; Manufacturer: Amphenol ICC / FCI
footprint CON: G97V24312HR (MCIO)
part A pins: A1, A2, A3, A4, A5, A6, A7, A8, A9, A10, A11, A12, A13, A14, A15, A16, A17, A18, A19, A20, A21, A22, A23, A24, A25, A26, A27, A28, A29, A30, A31, A32, A33, A34, A35, A36, A37, B1, B2, B3, B4, B5, B6, B7, B8, B9, B10, B11, B12, B13, B14, B15, B16, B17, B18, B19, B20, B21, B22, B23, B24, B25, B26, B27, B28, B29, B30, B31, B32, B33, B34, B35, B36, B37
part B pins: A38, A39, A40, A41, A42, A43, A44, A45, A46, A47, A48, A49, A50, A51, A52, A53, A54, A55, A56, A57, A58, A59, A60, A61, A62, B38, B39, B40, B41, B42, B43, B44, B45, B46, B47, B48, B49, B50, B51, B52, B53, B54, B55, B56, B57, B58, B59, B60, B61, B62

## HR911105A
designator X?  CommentText: Ethernet RJ-45
Ethernet RJ-45, 10/100 Mbit, 60VDC max, 8P8C; Manufacturer: Hanrun; PartNumber: HR911105A; TypeConnector: Etherner RJ-45 connector
footprint CON: HR911105A (RJ-45)
pins: 1 TD+, 2 TD-, 3 RD+, 4 CT, 5 CT, 6 RD-, 8 GND, 9 D2, 10 D1, 11 D3, 12 D4

## IDC-10
designator X?, comment Debug JTAG
Header, 10 pin, pitch 2.54mm, 250V, 2.5A, -55...120°C; Manufacturer: Connfly; PartNumber: IDC-10; Multichannel: 10pin
footprint CON: IDC-10MS (IDC-10MS 10 pin PCB-mount header)
pins: 1, 2, 3 (power), 4 (power), 5 (power), 6 (power), 7 (power), 8 (power), 9 (power), 10 (power)

## IDC-20
designator X?, comment 20 pin, 2.54 mm  (value not drawn)
Header, 20 pins, pitch 2.54mm, 250V, 2.5A, -55...120°C; Manufacturer: Connfly; PartNumber: IDC-20; Multichannel: 20 pins
footprint CON: IDC-20MS
pins: 1, 2, 3 (power), 4 (power), 5 (power), 6 (power), 7 (power), 8 (power), 9 (power), 10 (power), 11, 12, 13 (power), 14 (power), 15 (power), 16 (power), 17 (power), 18 (power), 19 (power), 20 (power)

## JST-1.25-2
designator X?, comment Connector
JST GH series, 2 pins, pitch 1.25 mm, 250V, -30...90°C; PartNumber: JST-1.25-2; Pitch: 1.25
footprint CON: JST-1.25 (2 pins)
pins: 1, 2

## JST-1.25-3
designator X?, comment Connector
JST GH series, 3 pins, pitch 1.25 mm, 250V, -30...90°C; PartNumber: JST-1.25-2; Pitch: 1.25
footprint CON: JST-1.25 (3 pins)
pins: 1, 2, 3

## JST-1.25-4
designator X?, comment Connector
JST GH series, 4 pins, pitch 1.25 mm, 250V, -30...90°C; PartNumber: JST-1.25-2; Pitch: 1.25
footprint CON: JST-1.25 (4 pins)
pins: 1, 2, 3, 4

## JST-1.25-5
designator X?, comment Connector
JST GH series, 5 pins, pitch 1.25 mm, 250V, -30...90°C; PartNumber: JST-1.25-2; Pitch: 1.25
footprint CON: JST-1.25 (5 pins)
pins: 1, 2, 3 (power), 4 (power), 5 (power)

## JST-1.25-6
designator X?, comment Connector
JST GH series, 6 pins, pitch 1.25 mm, 250V, -30...90°C; PartNumber: JST-1.25-2; Pitch: 1.25
footprint CON: JST-1.25 (6 pins)
pins: 1, 2, 3 (power), 4 (power), 5 (power), 6 (power)

## JST-1.25-8
designator X?, comment Connector
JST GH series, 8 pins, pitch 1.25 mm, 250V, -30...90°C; PartNumber: JST-1.25-2; Pitch: 1.25
footprint CON: JST-1.25 (8 pins)
pins: 1, 2, 3 (power), 4 (power), 5 (power), 6 (power), 7 (power), 8 (power)

## JST-1.25-10
designator X?, comment Connector
JST GH series, 10 pins, pitch 1.25 mm, 250V, -30...90°C; PartNumber: JST-1.25-2; Pitch: 1.25
footprint CON: JST-1.25 (10 pins)
pins: 1, 2, 3 (power), 4 (power), 5 (power), 6 (power), 7 (power), 8 (power), 9 (power), 10 (power)

## Jumper PCB
designator J?  (value not drawn)
Jumper PCB, 1 pin, ring diameter 1.00 mm
footprint CON: JUMPER x1
pins: 1 IN, 2

## Jumper PLS-2
designator J?  (value not drawn)
Jumper, 2 pins, 3A, pitch 2.54 mm; Manufacturer: Dealon; PartNumber: DZ254R-11-02-63
footprint CON: PLS-3
pins: 1 IN, 2

## Jumper PLS-2R
designator J?  (value not drawn)
Jumper, 2 pins, 3A, pitch 2.54 mm; Manufacturer: XFCN; PartNumber: PZ254R-11-02P
footprint CON: PLS-2R
pins: 1 IN, 2

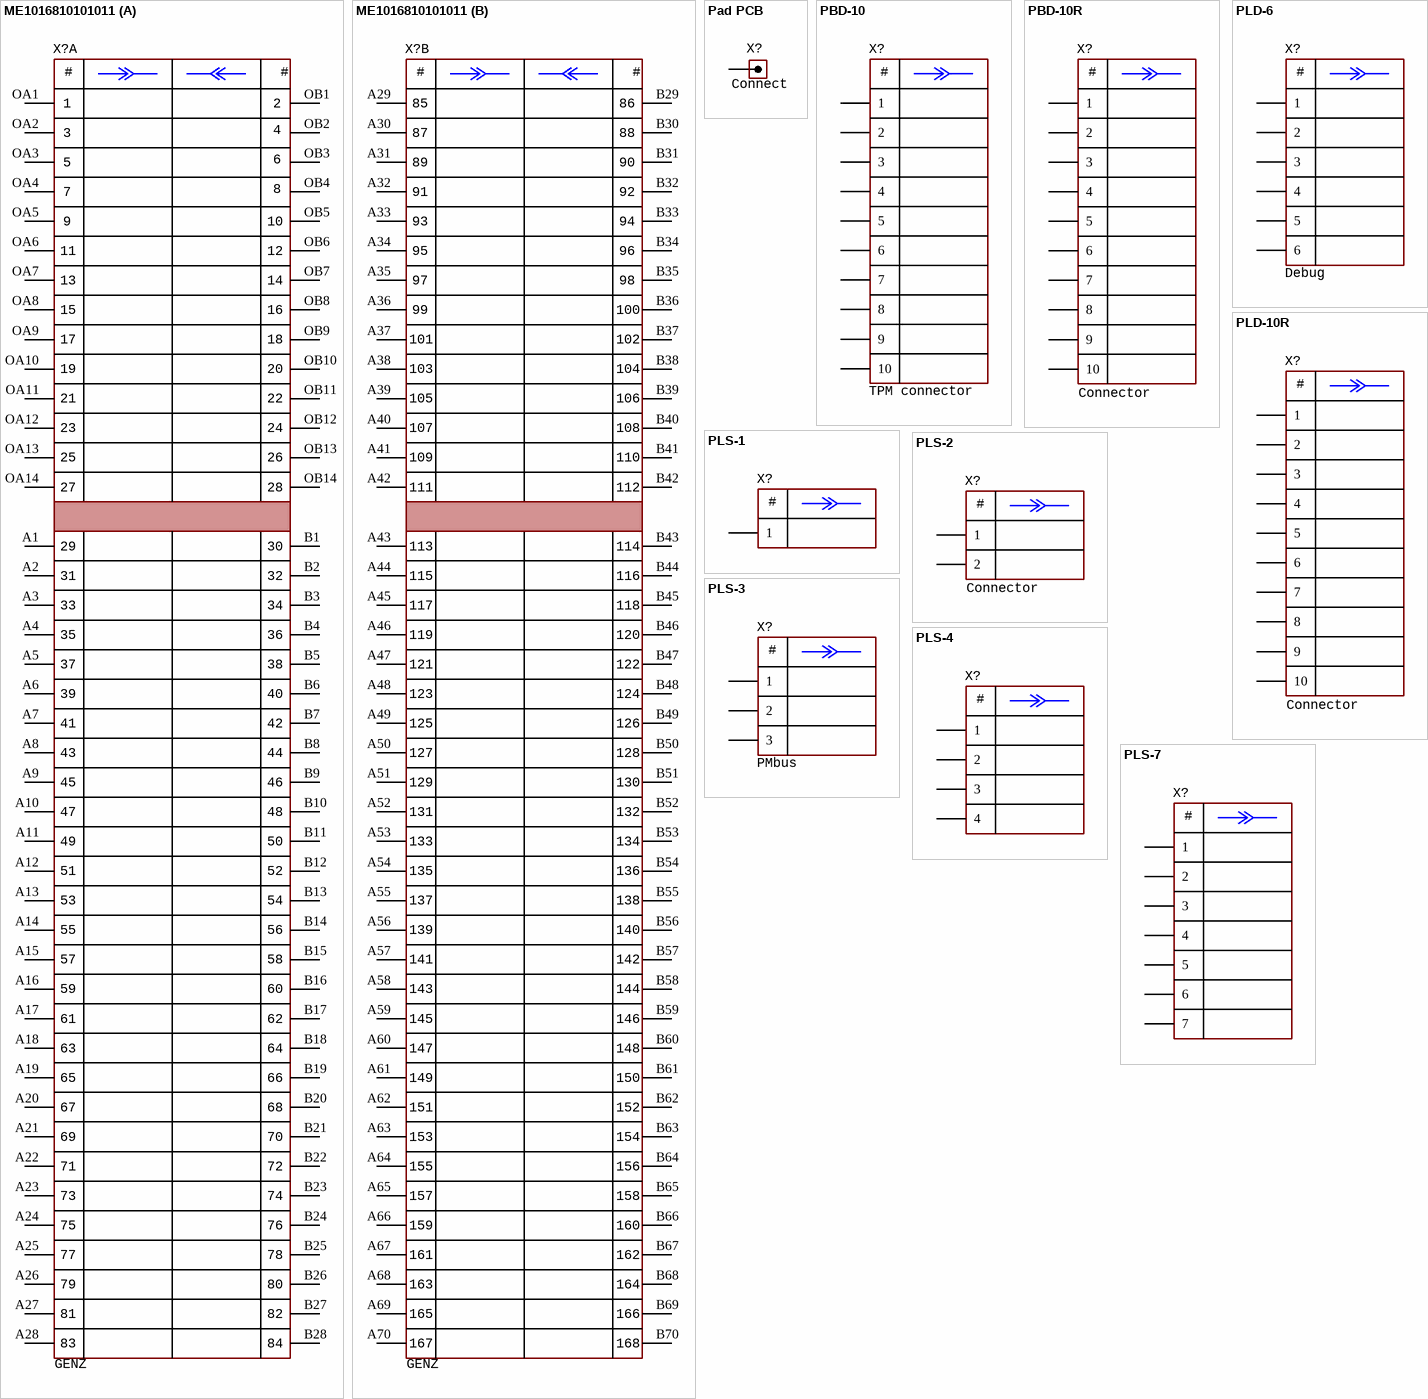
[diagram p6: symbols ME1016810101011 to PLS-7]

## ME1016810101011
designator X?, comment GENZ
GENZ, 168 pins, pitch 0.6 mm, 85 Omhs, vertical, -55...+85°C; Manufacturer: Amphenol; PartNumber: ME1016810101011; Manufacturer: AMPHENOL ICC (FCI)
footprint CON: ME1016810101011 (GENZ, OCP 3.0)
part A pins: A1, A2, A3, A4, A5, A6, A7, A8, A9, A10, A11, A12, A13, A14, A15, A16, A17, A18, A19, A20, A21, A22, A23, A24, A25, A26, A27, A28, B1, B2, B3, B4, B5, B6, B7, B8, B9, B10, B11, B12, B13, B14, B15, B16, B17, B18, B19, B20, B21, B22, B23, B24, B25, B26, B27, B28, OA1, OA2, OA3, OA4, OA5, OA6, OA7, OA8, OA9, OA10, OA11, OA12, OA13, OA14, OB1, OB2, OB3, OB4, OB5, OB6, OB7, OB8, OB9, OB10, OB11, OB12, OB13, OB14
part B pins: A29, A30, A31, A32, A33, A34, A35, A36, A37, A38, A39, A40, A41, A42, A43, A44, A45, A46, A47, A48, A49, A50, A51, A52, A53, A54, A55, A56, A57, A58, A59, A60, A61, A62, A63, A64, A65, A66, A67, A68, A69, A70, B29, B30, B31, B32, B33, B34, B35, B36, B37, B38, B39, B40, B41, B42, B43, B44, B45, B46, B47, B48, B49, B50, B51, B52, B53, B54, B55, B56, B57, B58, B59, B60, B61, B62, B63, B64, B65, B66, B67, B68, B69, B70

## Pad PCB
designator X?, comment Connect
Pad, 1 pin, pitch 2.54 mm; PartNumber: Testpoint
footprint CON: PAD 2.54 mm
pins: 1 IN

## PBD-10
designator X?  PartNumber: TPM connector  (hidden comment: PBD-10)
PBD, 10 pins, pitch 2.54 mm, 1A/pin, -40...+105°C; Manufacture: Connfly; Manufacturer: Samtec; Manufacturer Part Number: IPBD-10-D-R; Pitch: 2.54 mm
footprint CON: PBD-10
pins: 1, 2, 3 (power), 4 (power), 5 (power), 6 (power), 7 (power), 8 (power), 9 (power), 10 (power)

## PBD-10R
designator X?, comment Connector
PBD, 10 pins, pitch 2.54 mm, 1A/pin, -40...+105°C; Manufacture: Connfly; PartNumber: PBD-10R; Pitch: 2.54 mm
footprint CON: PBD-10R
pins: 1, 2, 3 (power), 4 (power), 5 (power), 6 (power), 7 (power), 8 (power), 9 (power), 10 (power)

## PLD-6
designator X?  PartNumber: Debug  (hidden comment: PLD-6)
6 pins, pitch 2.54 mm, 500VAC, 2A/pin, -40...+85°C; Manufacturer: Connfly; Pitch: 2.54mm
footprint CON: PLD-6
pins: 1, 2, 3 (power), 4 (power), 5 (power), 6 (power)

## PLD-10R
designator X?, comment Connector
10 pins, pitch 2.54 mm, 500VAC, 2A/pin, -40...+85°C; Manufacturer: Connfly; PartNumber: PLD-10R; Pitch: 2.54mm
footprint CON: PLD-10R
pins: 1, 2, 3 (power), 4 (power), 5 (power), 6 (power), 7 (power), 8 (power), 9 (power), 10 (power)

## PLS-1
designator X?, comment Debug #0  (value not drawn)
1 pin, pitch 2.54 mm, 3A/pin, 500VAC; PartNumber: PLS-1; Manufacturer: Connfly; Pitch: 2.54mm
footprint CON: PLS-1
pins: 1

## PLS-2
designator X?, comment Connector
2 pins, pitch 2.54 mm, 500VAC, 2A/pin, -40...+85°C; Manufacturer: Connfly; PartNumber: PLS-2; Manufacturer Part Number: PLS-3; Pitch: 2.54mm
footprint CON: PLS-2
pins: 1, 2

## PLS-3
designator X?, comment PMbus
3 pins, pitch 2.54 mm, 500VAC, 2A/pin, -40...+85°C; Manufacturer: Connfly; PartNumber: PLS-3; Pitch: 2.54mm
footprint CON: PLS-3
pins: 1, 2, 3 (power)

## PLS-4
designator X?, comment Debug #0  (value not drawn)
PLS connector, 4 pins, pitch 2.54 mm, 3A/pin, 500VAC; PartNumber: PLS-4; Manufacturer: Connfly; Manufacturer: Ningbo Connfly Electric; Manufacturer Part Number: DS1021-1*4SF1-1; Pitch: 2.54mm
footprint CON: PLS-4 (Connector) (PLS-4 pin header)
pins: 1, 2, 3 (power), 4 (power)

## PLS-7
designator X?, comment Debug #0  (value not drawn)
PLS connector, 7 pins, pitch 2.00 mm, 3A/pin, 500VAC; PartNumber: DS1025-01-1x7; Manufacturer: Connfly; Pitch: 2.00mm
footprint CON: PLS-7 (pitch 2.00 mm)
pins: 1, 2, 3 (power), 4 (power), 5 (power), 6 (power), 7 (power)

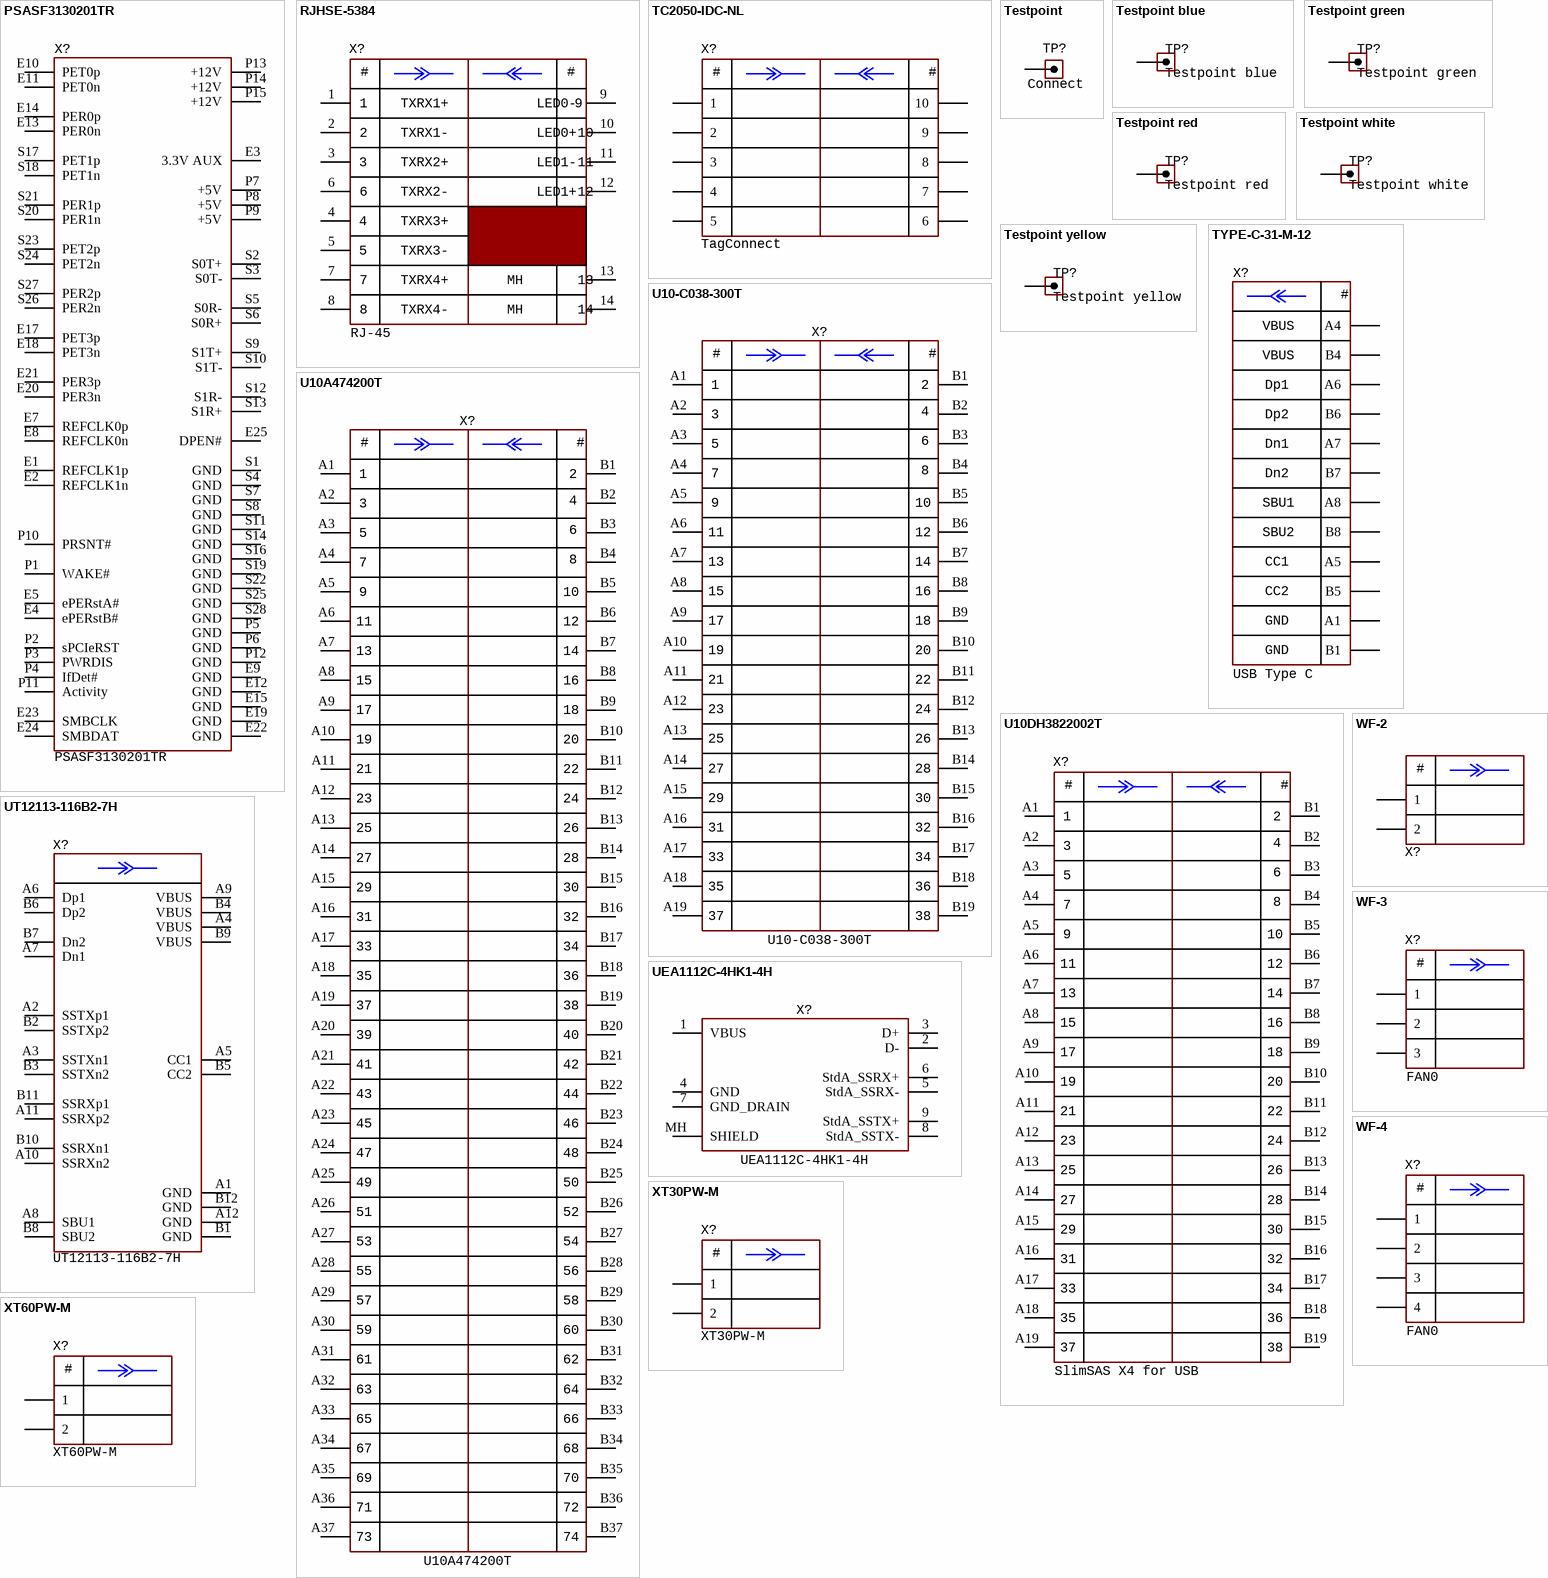
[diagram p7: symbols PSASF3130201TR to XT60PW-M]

## PSASF3130201TR
designator X?
U.2, 68 pins, 12G, 1.5A/pin, 0...+55°C; Manufacturer: Amphenol
footprint CON: PSASF3130201TR (NVME)
pins: E1 REFCLK1p, E2 REFCLK1n, E3 3.3V AUX, E4 ePERstB#, E5 ePERstA#, E7 REFCLK0p, E8 REFCLK0n, E9 GND, E10 PET0p, E11 PET0n, E12 GND, E13 PER0n, E14 PER0p, E15 GND, E17 PET3p, E18 PET3n, E19 GND, E20 PER3n, E21 PER3p, E22 GND, E23 SMBCLK, E24 SMBDAT, E25 DPEN#, P1 WAKE#, P2 sPCIeRST, P3 PWRDIS, P4 IfDet#, P5 GND, P6 GND, P7 +5V, P8 +5V, P9 +5V, P10 PRSNT#, P11 Activity, P12 GND, P13 +12V, P14 +12V, P15 +12V, S1 GND, S2 S0T+, S3 S0T-, S4 GND, S5 S0R-, S6 S0R+, S7 GND, S8 GND, S9 S1T+, S10 S1T-, S11 GND, S12 S1R-, S13 S1R+, S14 GND, S16 GND, S17 PET1p, S18 PET1n, S19 GND, S20 PER1n, S21 PER1p, S22 GND, S23 PET2p, S24 PET2n, S25 GND, S26 PER2n, S27 PER2p, S28 GND

## RJHSE-5384
designator X?, comment RJ-45
RJ45, 8p8c, Yellow/Green LED, -55...85°C; Manufacturer: Amphenol; Manufacturer: Amphenol Commercial
footprint CON: 615008137421 (RJ-45/Wurth)
pins: 1, 2, 3, 4, 5, 6, 7, 8, 9, 10, 11, 12, 13, 14

## TC2050-IDC-NL
designator X?  PartNumber: TagConnect  (hidden comment: TC2050-IDC-NL)
TagConnect, 10 pins, pitch 2.54 mm,; Manufacturer: Tag-Connect
footprint CON: TC2050-IDC-NL
pins: 1, 2, 3 (power), 4 (power), 5 (power), 6 (power), 7 (power), 8 (power), 9 (power), 10 (power)

## Testpoint
designator TP?, comment Connect
Testpoint, 1 pin, ring diameter 1.00 mm
footprint CON: PAD
pins: 1 IN

## Testpoint blue
designator TP?
Testpoint, 1 pin, blue bead, ring diameter 2.54 mm; Manufacturer: China
footprint Testpoint_ring_bead_blue
pins: 1 IN

## Testpoint green
designator TP?
Testpoint, 1 pin, green bead, ring diameter 2.54 mm; Manufacturer: China
footprint Testpoint_ring_bead_green
pins: 1 IN

## Testpoint red
designator TP?
Testpoint, 1 pin, red bead, ring diameter 2.54 mm; Manufacturer: China
footprint Testpoint_ring_bead_red
pins: 1 IN

## Testpoint white
designator TP?
Testpoint, 1 pin, white bead, ring diameter 2.54 mm; Manufacturer: China
footprint Testpoint_ring_bead_white
pins: 1 IN

## Testpoint yellow
designator TP?
Testpoint, 1 pin, yellow bead, ring diameter 2.54 mm; Manufacturer: China
footprint Testpoint_ring_bead_yellow
pins: 1 IN

## TYPE-C-31-M-12
designator X?, comment USB Type C
USB 3.1, Type C, 16 pins, 20V, 3.0A, -40...+85°C; Manufacturer: Korean Hroparts; PartNumber: TYPE-C-31-M-12
footprint CON: TYPE-C-31-M-12 (USB)
pins: A1, A4, A5, A6, A7, A8, B1, B4, B5, B6, B7, B8

## U10-C038-300T
designator X?
SlimSAS, x4 line, 38 pins, right angle; Manufacturer: Amphenol; Manufacturer: Amphenol Commercial; Multichannel: 38pin
footprint CON: U10-C038-300T (slimSAS 38 pin) (Amphenol)
pins: A1, A2, A3, A4, A5, A6, A7, A8, A9, A10, A11, A12, A13, A14, A15, A16, A17, A18, A19, B1, B2, B3, B4, B5, B6, B7, B8, B9, B10, B11, B12, B13, B14, B15, B16, B17, B18, B19

## U10A474200T
designator X?
SlimSAS, x8 line, 74 pins, 0.5A/pin, 24 GT/s, Right angle, -55...+85°C; Manufacturer: Amphenol; Multichannel: 74pin
footprint CON: 2356320-1 (slimSAS: or U10A474200T) (TE manufacture)
pins: A1, A2, A3, A4, A5, A6, A7, A8, A9, A10, A11, A12, A13, A14, A15, A16, A17, A18, A19, A20, A21, A22, A23, A24, A25, A26, A27, A28, A29, A30, A31, A32, A33, A34, A35, A36, A37, B1, B2, B3, B4, B5, B6, B7, B8, B9, B10, B11, B12, B13, B14, B15, B16, B17, B18, B19, B20, B21, B22, B23, B24, B25, B26, B27, B28, B29, B30, B31, B32, B33, B34, B35, B36, B37

## U10DH3822002T
designator X?, comment SlimSAS X4 for USB
SlimSAS, x4 line, 38 pins, 24 GT/s, verticale; PartNumber: U10DH3822002T; Manufacturer: Amphenol; Multichannel: 38pin
footprint CON: U10DH3822002T (SlimSAS x4) (Amphenol)
pins: A1, A2, A3, A4, A5, A6, A7, A8, A9, A10, A11, A12, A13, A14, A15, A16, A17, A18, A19, B1, B2, B3, B4, B5, B6, B7, B8, B9, B10, B11, B12, B13, B14, B15, B16, B17, B18, B19

## UEA1112C-4HK1-4H
designator X?
USB 3.0, 9 pins, 30V, 1.8A, -20...+85°C; Manufacturer: Foxconn
footprint CON: UEA1112C-4HK1-4H (USB)
pins: 1 VBUS, 2 D-, 3 D+, 4 GND, 5 StdA_SSRX-, 6 StdA_SSRX+, 7 GND_DRAIN, 8 StdA_SSTX-, 9 StdA_SSTX+, MH SHIELD

## UT12113-116B2-7H
designator X?
USB 3.1, Type C, 24 pins, 20V, 3.0A, -40...+85°C; Manufacturer: Foxconn
footprint CON: UT12113-116B2-7H (USB type C)
pins: A1 GND, A2 SSTXp1, A3 SSTXn1, A4 VBUS, A5 CC1, A6 Dp1, A7 Dn1, A8 SBU1, A9 VBUS, A10 SSRXn2, A11 SSRXp2, A12 GND, B1 GND, B2 SSTXp2, B3 SSTXn2, B4 VBUS, B5 CC2, B6 Dp2, B7 Dn2, B8 SBU2, B9 VBUS, B10 SSRXn1, B11 SSRXp1, B12 GND

## WF-2
designator X?, comment FAN  (value not drawn)
WF series, 2 pin, pitch 2.54 mm, 250V, -30...90°C; Manufacturer: Connfly; PartNumber: WF-2; Pitch: 2.54mm
footprint CON: WF-02
pins: 1, 2

## WF-3
designator X?, comment FAN0
WF series, 3 pin, pitch 2.54 mm, 250V, -30...90°C; PartNumber: WF-3; Manufacturer: Connfly; Pitch: 2.54mm
footprint CON: WF-03
pins: 1, 2, 3

## WF-4
designator X?, comment FAN0
WF series, 4 pin, pitch 2.54 mm, 250V, -30...90°C; PartNumber: WF-4; Manufacturer: Connfly; Pitch: 2.54mm
footprint CON: WF-04
pins: 1, 2, 3, 4

## XT30PW-M
designator X?
XT series, 30A, 2 pin, 500VDC, pitch 5.0 mm; Manufacturer: AMASS; Manufacturer: Unclassified; Pitch: 5.0mm
footprint CON: XT30PW-M
pins: 1, 2

## XT60PW-M
designator X?
XT series, 60A, 2 pin, 500VDC, pitch 5.0 mm; Manufacturer: AMASS; Pitch: 5.0mm
footprint CON: XT60PW-M
pins: 1, 2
